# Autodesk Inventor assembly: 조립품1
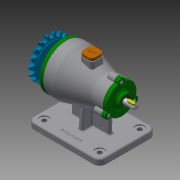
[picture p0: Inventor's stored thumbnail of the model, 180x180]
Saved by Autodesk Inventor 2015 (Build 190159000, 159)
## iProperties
Created: 2021-10
Part Number: 조립품1
Document SubType Name: Assembly
Designer: 1016549
Author: 1016549
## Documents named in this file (17)
- C:\Users\1016549\Desktop\711006V1011\조립품1.iam
- C:\Users\1016549\Desktop\711006V1011\Ű 5x5.ipt
- 키 5 x 5.ipt
- C:\Users\1016549\Desktop\711006V1011\뒤커버.ipt
- C:\Users\1016549\Desktop\711006V1011\마개.ipt
- C:\Users\1016549\Desktop\711006V1011\베어링 6200.ipt
- C:\Users\1016549\Desktop\711006V1011\베어링 6203.ipt
- C:\Users\1016549\Desktop\711006V1011\본체.ipt
- C:\Users\1016549\Desktop\711006V1011\볼트 M4.ipt
- 볼트 M4 x 12.ipt
- C:\Users\1016549\Desktop\711006V1011\스프로킷.ipt
- C:\Users\1016549\Desktop\711006V1011\앞커버.ipt
- C:\Users\1016549\Desktop\711006V1011\오일 실 10x20x7.ipt
- C:\Users\1016549\Desktop\711006V1011\오일 실 17x30x8.ipt
- C:\Users\1016549\Desktop\711006V1011\와셔.ipt
- C:\Users\1016549\Desktop\711006V1011\축.ipt
- C:\Users\1016549\Desktop\711006V1011\키 5x5.ipt
## Component patterns: 구성요소 패턴 1:2 (3 elements), 구성요소 패턴 1:3 (3 elements), 구성요소 패턴 1:4 (3 elements), 구성요소 패턴 4:2 (6 elements), 구성요소 패턴 4:3 (6 elements), 구성요소 패턴 4:4 (6 elements), 구성요소 패턴 4:5 (6 elements), 구성요소 패턴 4:6 (6 elements)
